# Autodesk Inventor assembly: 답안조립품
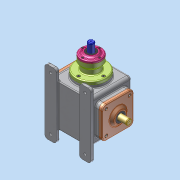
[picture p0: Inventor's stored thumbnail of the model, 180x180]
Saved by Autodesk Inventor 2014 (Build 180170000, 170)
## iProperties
Created: 2026-01
Part Number: 답안조립품
Document SubType Name: Assembly
Designer: dg
Author: dg
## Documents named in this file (16)
- C:\Users\dg\Desktop\760103V1003\답안조립품.iam
- C:\Users\dg\Desktop\760103V1003\본체.ipt
- C:\Users\dg\Desktop\760103V1003\가져온 구성요소\구동축\구동축.ipt
- C:\Users\dg\Desktop\760103V1003\가져온 구성요소\종동축\종동축.ipt
- C:\Users\dg\Desktop\760103V1003\가져온 구성요소\평행 키 6x6x18\평행 키 6x6x18.ipt
- C:\Users\dg\Desktop\760103V1003\가져온 구성요소\베벨 기어(구동)\베벨 기어(구동).ipt
- C:\Users\dg\Desktop\760103V1003\가져온 구성요소\베벨 기어(종동)\베벨 기어(종동).ipt
- C:\Users\dg\Desktop\760103V1003\가져온 구성요소\베어링 하우징\베어링 하우징.ipt
- C:\Users\dg\Desktop\760103V1003\가져온 구성요소\테이퍼 롤러 베어링 30204K\테이퍼 롤러 베어링 30204K.ipt
- C:\Users\dg\Desktop\760103V1003\가져온 구성요소\칼라\칼라.ipt
- C:\Users\dg\Desktop\760103V1003\가져온 구성요소\하우징 커버\하우징 커버.ipt
- C:\Users\dg\Desktop\760103V1003\가져온 구성요소\측면 커버\측면 커버.ipt
- C:\Users\dg\Desktop\760103V1003\가져온 구성요소\엔드캡\엔드캡.ipt
- C:\Users\dg\Desktop\760103V1003\가져온 구성요소\6각 구멍붙이 볼트 M4x10\6각 구멍붙이 볼트 M4x10.ipt
- C:\Users\dg\Desktop\760103V1003\가져온 구성요소\6각 구멍붙이 볼트 M6x12\6각 구멍붙이 볼트 M6x12.ipt
- C:\Users\dg\Desktop\760103V1003\가져온 구성요소\오일 실 20 35 8\오일 실 20 35 8.ipt
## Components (19 placed, 4 different names)
1. 구동축:1
2. 하우징 커버:1
3. 6각 구멍붙이 볼트 M6x12:1
4. 6각 구멍붙이 볼트 M6x12:3
5. 6각 구멍붙이 볼트 M6x12:5
6. 6각 구멍붙이 볼트 M6x12:6
7. 6각 구멍붙이 볼트 M6x12:7
8. 6각 구멍붙이 볼트 M4x10:1
9. 6각 구멍붙이 볼트 M4x10:2
10. 6각 구멍붙이 볼트 M4x10:3
11. 6각 구멍붙이 볼트 M4x10:4
12. 6각 구멍붙이 볼트 M6x12:2
13. 6각 구멍붙이 볼트 M6x12:8
14. 6각 구멍붙이 볼트 M6x12:9
15. 6각 구멍붙이 볼트 M6x12:10
16. 6각 구멍붙이 볼트 M6x12:4
17. 6각 구멍붙이 볼트 M6x12:11
18. 6각 구멍붙이 볼트 M6x12:12
19. 6각 구멍붙이 볼트 M6x12:13
